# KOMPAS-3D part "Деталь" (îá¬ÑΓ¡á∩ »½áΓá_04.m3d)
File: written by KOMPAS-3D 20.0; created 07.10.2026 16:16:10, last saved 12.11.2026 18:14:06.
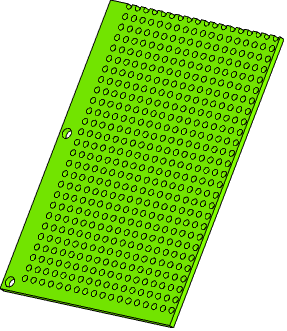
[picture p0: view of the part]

Document properties: Полное имя файла: D:\myProjects\Progect_esp32\box_compas\макетки\Макетная плата_04.m3d

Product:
- Part/product: Деталь
    Масса: 0.0310587

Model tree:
1. Эскиз:1
2. Элемент выдавливания:1
     Расстояние 1 = 1.5
3. Эскиз:2  (with: Элемент выдавливания:1)
4. Элемент выдавливания:2
     Расстояние 2 = 1.5
5. Эскиз:3  (with: Элемент выдавливания:1)
6. Элемент выдавливания:3
     Расстояние 2 = 1.5
7. Массив по сетке:1  (with: Элемент выдавливания:3, Эскиз:3, Элемент выдавливания:1)  (540 pattern instances)
     Шаг 1 = 2.54; Угол раствора = -90; Шаг 2 = 2.54
8. Массив по сетке:2  (with: Элемент выдавливания:2, Эскиз:2, Элемент выдавливания:1)  (4 pattern instances)
     Шаг 1 = 56; Угол раствора = 90; Шаг 2 = 36; Геометрический массив = 128
9. Эскиз:4  (with: Элемент выдавливания:1)
10. Элемент выдавливания:4
     Расстояние 2 = 1.5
